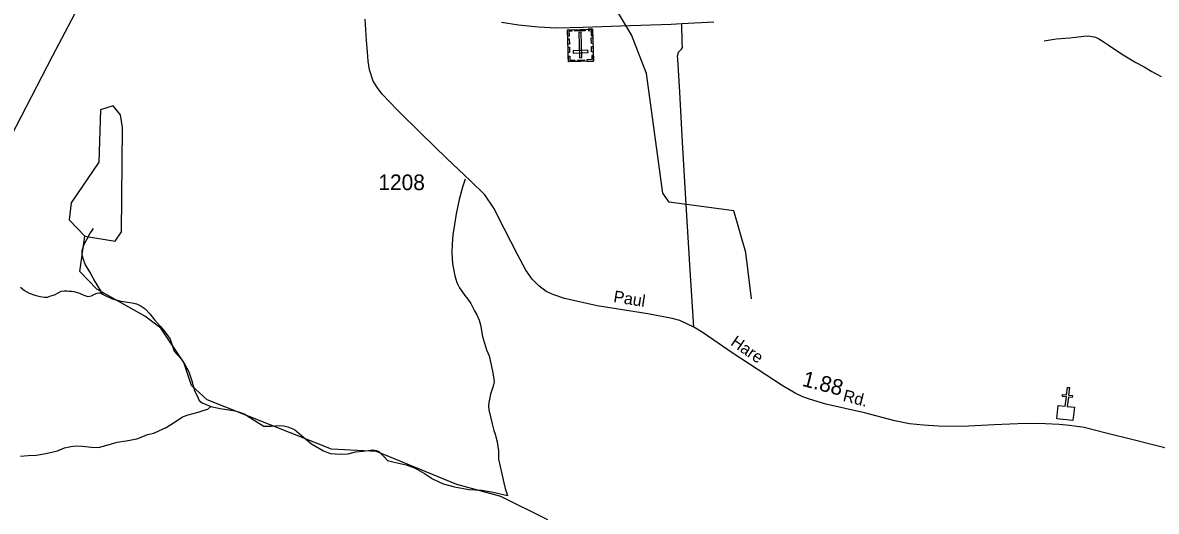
# Model space of a CAD drawing. Extents: x 2206922 to 2357709, y 510027 to 673830.
# Drawn here: x 2232663 to 2241724, y 565687 to 569592 of the extents above; entities that cross this region are included whole.
import ezdxf

# ---------------------------------------------------------------- set-up
doc = ezdxf.new("R2010")
doc.units = 0
for name, color, linetype in [('Exist Cultural Cemetery CELL', 7, 'Continuous'), ('Exist Cultural Church CELL', 7, 'Continuous'), ('Exist Hydrographic Creek Single Shore', 7, 'Continuous'), ('Exist Hydrographic Misc Water Feature', 7, 'Continuous'), ('Exist Hydrographic Pond Under 1500 Sq Ft', 7, 'Continuous'), ('Exist Road Non-System Type 51', 7, 'Continuous'), ('Exist Road Secondary Mileage Hundredths English Label', 7, 'Continuous'), ('Exist Road Secondary Type 51 Attributed', 7, 'Continuous'), ('Exist Road Secondary Type 51 Label', 7, 'Continuous'), ('Exist Road Secondary Type 51 Number Label', 7, 'Continuous')]:
    doc.layers.add(name, color=color, linetype=linetype)

msp = doc.modelspace()

# ---------------------------------------------------------------- linework, layer by layer
at = {"layer": 'Exist Cultural Cemetery CELL'}
for points in [[(2237224.1, 569285.9), (2237025.1, 569280.3), (2237017.9, 569534.8), (2237216.9, 569540.4)], [(2237051, 569535.7), (2237051.3, 569524.3), (2237029.3, 569523.6), (2237030.5, 569483.2), (2237019.4, 569482.9), (2237017.9, 569534.8)], [(2237031.3, 569462.9), (2237032.5, 569419.6), (2237021.1, 569419.3), (2237019.9, 569462.6)], [(2237159.8, 569527.3), (2237075, 569524.9), (2237074.6, 569536.3), (2237159.5, 569538.7)], [(2237114.3, 569312.1), (2237133, 569312.6), (2237127.2, 569515.3), (2237108.6, 569514.8)], [(2237183.8, 569539.4), (2237184.2, 569528), (2237206.2, 569528.6), (2237207.3, 569488.2), (2237218.4, 569488.5), (2237217, 569540.4)], [(2237218.9, 569470.5), (2237220.1, 569427.2), (2237208.8, 569426.9), (2237207.5, 569470.2)], [(2237033.1, 569397), (2237034.4, 569353.7), (2237023, 569353.4), (2237021.8, 569396.7)], [(2237181.4, 569352.8), (2237180.8, 569371.4), (2237063.2, 569368.1), (2237063.7, 569349.4)], [(2237220.8, 569403.3), (2237222, 569360), (2237210.6, 569359.7), (2237209.4, 569403)], [(2237023.8, 569323.6), (2237035.1, 569323.9), (2237036, 569291.8), (2237076.6, 569292.9), (2237076.9, 569281.8), (2237025, 569280.3)], [(2237150.1, 569283.8), (2237098.2, 569282.4), (2237097.9, 569293.7), (2237149.7, 569295.2)], [(2237222.9, 569329.2), (2237211.5, 569328.9), (2237212.4, 569296.7), (2237171.9, 569295.6), (2237172.2, 569284.4), (2237224.1, 569285.9)]]:
    msp.add_lwpolyline(points, close=True, dxfattribs=at)
at = {"layer": 'Exist Cultural Church CELL'}
msp.add_lwpolyline([(2240939.5, 566532.7), (2240996.1, 566526.6), (2241004.5, 566602.3), (2240972.7, 566605.8), (2240974.4, 566621.7), (2241006.2, 566618.1), (2241012.9, 566677.9), (2241028.8, 566676.2), (2241022.2, 566616.4), (2241054, 566612.9), (2241052.2, 566597), (2241020.4, 566600.5), (2241012, 566524.8), (2241069.3, 566518.4), (2241057.6, 566412.6), (2240927.8, 566426.9)], close=True, dxfattribs=at)
at = {"layer": 'Exist Hydrographic Creek Single Shore'}
for points in [[(2240827, 569447.6), (2240923, 569464.4), (2241032.9, 569471.3), (2241144.6, 569484), (2241178.7, 569486.6), (2241210.7, 569482.6), (2241236.7, 569475.1), (2241264.8, 569463.1), (2241291.2, 569447.4), (2241339, 569415.8), (2241445.9, 569342.5), (2241560.3, 569273.7), (2241626.5, 569238.2), (2241688.6, 569202.9), (2241761.2, 569161.1)], [(2236861.3, 565618.2), (2236484.2, 565806.2), (2236133.2, 565901.8), (2235490.1, 566164.1), (2235132.1, 566184.4), (2234137.2, 566578.4), (2234011.3, 566692.5), (2233952.2, 566877.4), (2233766.2, 567150.1), (2233640.1, 567247.7), (2233256.1, 567462.1), (2233121.1, 567602.6), (2233160.1, 567887.1)]]:
    msp.add_lwpolyline(points, dxfattribs=at)
at = {"layer": 'Exist Hydrographic Misc Water Feature'}
for points in [[(2238487.2, 567385.9), (2238442.3, 567754.2), (2238348.1, 568087.4), (2237831.2, 568156.8), (2237780.1, 568230), (2237648.3, 569187.1), (2237529.2, 569494.6), (2237317.1, 569853), (2237292.1, 569952), (2237546.2, 570478.2), (2237610.1, 570729.4), (2237621.2, 571460.6), (2237645.2, 571594.6), (2237626.1, 571837.7), (2237656.3, 572253.6), (2237769.3, 572753.1), (2237834.3, 572886.3), (2237958.1, 573005.1), (2238464.2, 573217.9), (2238705.1, 573393.4), (2238829, 573531)], [(2236198.4, 568340.3), (2236177, 568278.3), (2236152.2, 568180.3), (2236128.4, 568065.8), (2236113.3, 567979.7), (2236100.1, 567895.7), (2236096.7, 567823.7), (2236093.4, 567755.6), (2236098.1, 567664.1), (2236116.8, 567570), (2236133, 567516.4), (2236153.7, 567472.4), (2236196.1, 567412.8), (2236220.1, 567382.9), (2236244.5, 567349.2), (2236275.1, 567289.5), (2236291.5, 567257.8), (2236311.8, 567213.7), (2236322, 567176.1), (2236337, 567084.2), (2236371.2, 566976.4), (2236390.1, 566928.6), (2236404.2, 566868.9), (2236419, 566807), (2236427.2, 566761.2), (2236431.9, 566723.2), (2236423.7, 566687.1), (2236402.4, 566623), (2236388.9, 566556.9), (2236385.2, 566526.7), (2236389.5, 566496.8), (2236416.3, 566386.9), (2236428.6, 566333.2), (2236438.9, 566303.2), (2236455.5, 566241.5), (2236461.9, 566205.7), (2236466, 566169.8), (2236466.8, 566103.5), (2236493.6, 565986), (2236508.4, 565916), (2236520.3, 565868.4), (2236536.9, 565814.4)], [(2233225.1, 567946.6), (2233211.2, 567922.3), (2233201.1, 567910), (2233187.8, 567886.1), (2233152.1, 567819.7), (2233140.6, 567783.7), (2233136.5, 567767.7), (2233136.5, 567757.6), (2233136.7, 567745.8), (2233138.8, 567727.7), (2233145.1, 567709.7), (2233161.3, 567656.1), (2233204, 567588.4), (2233240.7, 567524.5), (2233301.6, 567423.3)], [(2232645.2, 567479.7), (2232677.2, 567452.2), (2232713.7, 567430.5), (2232759.4, 567414.6), (2232801.7, 567403.4), (2232837.8, 567397.5), (2232862, 567399.6), (2232887.6, 567407.9), (2232917.7, 567418.3), (2232945.4, 567434.4), (2232971.5, 567446.7), (2232993.4, 567448.7), (2233015.1, 567449), (2233033, 567447.1), (2233053.5, 567445.3), (2233073.2, 567443.6), (2233097.4, 567435.4), (2233117.3, 567429.6), (2233151.7, 567413.9), (2233183.7, 567404.2), (2233213.2, 567408.6), (2233237.2, 567422.8), (2233257.3, 567430.8), (2233279.4, 567433.1)], [(2233279.4, 567433.1), (2233283.1, 567435), (2233301.6, 567423.3)], [(2233301.6, 567423.3), (2233321.7, 567411.3), (2233377.7, 567385.8), (2233447.6, 567366.4), (2233538, 567353.1), (2233573.7, 567345.3), (2233602.2, 567331.7), (2233642.2, 567304.2), (2233680.1, 567264.4), (2233716.8, 567218.7), (2233765.2, 567163.1), (2233809.5, 567107.4), (2233841.9, 567064), (2233858.5, 567016.1), (2233874.9, 566966.1), (2233929.1, 566906.5), (2233959.8, 566860.9), (2233990.2, 566801.1), (2234014.8, 566729.3), (2234037.1, 566653.7), (2234065.4, 566591.9), (2234074, 566571.9), (2234098.2, 566554.1), (2234166.1, 566524.8)], [(2232646.5, 566128.3), (2232706.3, 566133.1), (2232770.1, 566135.6), (2232847.6, 566150.3), (2232941.7, 566171), (2232997.7, 566193.4), (2233047.3, 566205.8), (2233091.4, 566210), (2233141.2, 566208.6), (2233213.2, 566198.9), (2233269.6, 566197.3), (2233327.2, 566212.2), (2233417, 566240.8), (2233490.9, 566249.5), (2233574.7, 566266.1), (2233622.3, 566284.4), (2233660.4, 566300.6), (2233710.5, 566312.9), (2233750, 566329.2), (2233809.7, 566358), (2233897.5, 566412.4), (2233939.1, 566441.1), (2233986.9, 566459.4), (2234066.8, 566479.8), (2234112.6, 566494.4), (2234142.3, 566504.5), (2234166.1, 566524.8)], [(2234166.1, 566524.8), (2234242.6, 566509.2), (2234360.5, 566490.2), (2234396.4, 566480.7), (2234432.9, 566465.1), (2234482.7, 566435.3), (2234543.4, 566395.7), (2234591.4, 566368.2), (2234649.4, 566368.8), (2234711.3, 566373.2), (2234751.1, 566369.6), (2234781.3, 566361.9), (2234835.4, 566340.3), (2234892.2, 566292.9), (2234970.5, 566227.5), (2235066.9, 566170.4), (2235121, 566148.8), (2235200.8, 566143.3), (2235265, 566147.8), (2235322.6, 566162.2), (2235384.9, 566168.6), (2235460.4, 566177.5), (2235488.7, 566173.7), (2235510.8, 566163.8), (2235546.9, 566128), (2235579.1, 566092.3), (2235631.4, 566078.7), (2235727.2, 566059.8), (2235799.5, 566032.3), (2235874, 565989), (2235937.9, 565947.3), (2236022.6, 565906.2), (2236114.7, 565883), (2236228.5, 565861.7), (2236332.7, 565856.6), (2236424.5, 565839.4), (2236536.9, 565814.4)]]:
    msp.add_lwpolyline(points, dxfattribs=at)
at = {"layer": 'Exist Hydrographic Pond Under 1500 Sq Ft'}
msp.add_lwpolyline([(2233160.1, 567887.1), (2233402.1, 567846.2), (2233452.1, 567920.6), (2233461.1, 568753.5), (2233444.1, 568855.5), (2233385.3, 568928.9), (2233286.2, 568894.8), (2233272.1, 568478.5), (2233050.2, 568151.8), (2233034.2, 568017.6), (2233160.1, 567887.1)], dxfattribs=at)
at = {"layer": 'Exist Road Non-System Type 51'}
msp.add_lwpolyline([(2238026.6, 567158), (2237997.7, 567613.5), (2237965.3, 568139), (2237937.4, 568638.6), (2237916, 569036.3), (2237900, 569301.9), (2237897.7, 569326), (2237901.6, 569341.9), (2237905.5, 569356), (2237915.3, 569368), (2237927.4, 569380.1), (2237935.3, 569394.2), (2237934.9, 569434.2), (2237931.6, 569586)], dxfattribs=at)
at = {"layer": 'Exist Road Secondary Type 51 Attributed'}
for points in [[(2233690.2, 570829.9), (2233665.9, 570778.7), (2232899.9, 569321.9), (2232569.5, 568682.9), (2232436, 568443.3), (2232353.5, 568284), (2232292.2, 568175.7), (2232215.5, 568018.4), (2232163.7, 567885), (2232115.8, 567734.4), (2232052.5, 567569.5), (2231995, 567400.7), (2231964.3, 567306.7), (2231947.9, 567198.5), (2231927.8, 566956.4), (2231912.9, 566568.4), (2231901.1, 566306.5), (2231887.7, 565992.5), (2231876.1, 565887.1), (2231832, 565647.3)], [(2241863.7, 566175.7), (2241539.1, 566259), (2241322.8, 566311.2), (2241146.4, 566357.8), (2241030.3, 566372.7), (2240946.3, 566382), (2240838.3, 566387.2), (2240678.3, 566387.8), (2240428.6, 566377.9), (2240170.8, 566363.7), (2239982.9, 566368.3), (2239862.9, 566375.3), (2239750.8, 566386.4), (2239632.7, 566409.4), (2239392.2, 566473.4), (2239082.4, 566544.6), (2238952.8, 566583.2), (2238899.6, 566601.3), (2238837.4, 566630.8), (2238732.9, 566693.2), (2238603.3, 566777.7), (2238342.6, 566949.6), (2238093.6, 567118.5), (2238026.6, 567158), (2237965.5, 567187.9), (2237914.5, 567211.2), (2237853.3, 567228.6), (2237660.7, 567265), (2237254.4, 567329.6), (2236994, 567387.4), (2236907.8, 567416.8), (2236847.6, 567444.2), (2236789.3, 567489.7), (2236734.8, 567541.2), (2236684.3, 567614.8), (2236617.2, 567740.1), (2236510.7, 567946.2), (2236427.7, 568108.7), (2236356.3, 568216.5), (2236241.3, 568328.7), (2236053.4, 568507.9), (2235851, 568704.6), (2235658.8, 568892.6), (2235535, 569021.5), (2235500.1, 569071.1), (2235463.7, 569124.2), (2235436, 569215.3), (2235424.3, 569284.5), (2235420, 569358.1), (2235411.9, 569449.6), (2235400.6, 569619.4)], [(2236490.2, 569596.3), (2236626.3, 569575.4), (2236786.3, 569558.8), (2236926.4, 569551.9), (2237142.2, 569557.6), (2237442.1, 569566.1), (2237845.7, 569581.3), (2237931.6, 569586), (2238187.4, 569600.2)]]:
    msp.add_lwpolyline(points, dxfattribs=at)

# ---------------------------------------------------------------- texts
at = {"layer": 'Exist Road Secondary Mileage Hundredths English Label'}
msp.add_text('1.88', height=125, rotation=345.62088, dxfattribs=at).set_placement((2238886.3, 566690.6))
at = {"layer": 'Exist Road Secondary Type 51 Label'}
for s, rotation, p in [('Paul', 350.96585, (2237380.3, 567359.4)), ('Hare', 325.57175, (2238314.3, 567020.3)), ('Rd.', 345.62088, (2239212.7, 566570.2))]:
    msp.add_text(s, height=95, rotation=rotation, dxfattribs=at).set_placement(p)
at = {"layer": 'Exist Road Secondary Type 51 Number Label'}
msp.add_text('1208', height=125, dxfattribs=at).set_placement((2235505.7, 568254))

doc.saveas('drawing.dxf')
